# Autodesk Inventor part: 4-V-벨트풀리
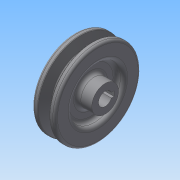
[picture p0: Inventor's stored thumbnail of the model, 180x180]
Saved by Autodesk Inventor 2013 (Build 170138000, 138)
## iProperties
Created: 2015-02
Part Number: 4-V-벨트풀리
Material: 일반
Document SubType Name: Modeling
Designer: Administrator
Density: 1 g/cm^3
Author: Administrator
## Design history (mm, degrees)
sketch "스케치1"
  geometry: L1 (0, 0)-(25, 0); L2 (0, 0)-(0, 11); L3 (0, 11)-(6, 11); L4 (13, 11)-(25, 11); L5 (25, 11)-(25, 0); L6 (6, 11)-(6, 21.5); L7 (6, 21.5)-(0, 21.5); L8 (0, 21.5)-(0, 35.2); L9 (0, 35.2)-(4.675, 35.2); L10 (4.675, 35.2)-(7.426, 26.2); L11 (7.426, 26.2)-(11.574, 26.2); L12 (11.574, 26.2)-(14.325, 35.2); L13 (14.325, 35.2)-(19, 35.2); L14 (19, 35.2)-(19, 21.5); L15 (19, 21.5)-(13, 21.5); L16 (13, 21.5)-(13, 11); 2 further points
  constraints: 32 end point, 7 parallel, 6 equal length, 4 perpendicular, 2 collinear, 2 horizontal, 2 point on line, 1 horizontal alignment
  dimensions: "d0" = 25 distance of L1.start L1.end; "d1" = 22 diameter of L4 L1; "d6" = 6 distance of L2.end L3.end; "d7" = 43 diameter of L7 L1; "d8" = 2.7 distance from line of point (5.5, 32.5) L9; "d9" = 6.3 distance from line of L11 point (5.5, 32.5); "d10" = 34 deg angle of L12 L10; "d11" = 8 distance of point (13.5, 32.5) point (5.5, 32.5); "d12" = 65 diameter of point (5.5, 32.5) L1; "d13" = 19 distance between parallel lines of L14 L8
revolve "회전1" sketch "스케치1" stored, may be unused: angle "d14" = 90 deg
sketch "스케치2"
  geometry: L1 (-2, 5.123)-(-2, 7.3); L2 (-2, 7.3)-(2, 7.3); L3 (2, 7.3)-(2, 5.123); C1 r 11 at (0, 0) reference; A1 r 5.5 centre (0, 0) between (-2, 5.123) and (2, 5.123)
  constraints: 6 end point, 2 parallel, 2 point on circle, 1 centre point, 1 coincident, 1 perpendicular, 1 vertical
  dimensions: "d15" = 11 diameter of A1; "d17" = 4 distance of L1.end L2.end; "d18" = 12.8 dimension on A1 L2
extrude "돌출1" cut sketch "스케치2" stored distance "d19" = 10; taper "d20" = 0 deg
fillet "모깎기1" dims "d21" = 0.5, "d22" = 1, "d23" = 2
fillet "모깎기2" dims "d24" = 3
node "솔리드1"
